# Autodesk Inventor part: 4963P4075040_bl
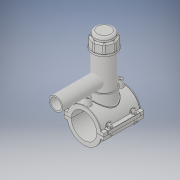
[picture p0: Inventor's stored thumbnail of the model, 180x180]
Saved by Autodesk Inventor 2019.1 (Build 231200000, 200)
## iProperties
Created: 2017-07
Part Number: 4963P4075040_bl
Material: Generic
Document SubType Name: Modeling
Designer: KIM
Density: 1 g/cm^3
Appearance: Default
Author: KIM
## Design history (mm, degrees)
derived "4963P4.ipt"
feature "Solid1::4963P4.ipt" dims "ScaleForDerivedMember" = 10
feature "Solid2::4963P4.ipt" dims "ScaleForDerivedMember" = 10
feature "Solid3::4963P4.ipt" dims "ScaleForDerivedMember" = 10
tag "TaggingFeature1"
body "Solid1"
body "Solid2"
body "Solid3"
other parameters: "d0" = 75 [user parameter], "d2" = 117 [user parameter], "d3" = 18.75 [user parameter], "d4" = 118 [user parameter], "d5" = 0 [user parameter], "d6" = 0.1 [user parameter], "d8" = 0 [user parameter], "d19" = 6 [user parameter], "d20" = 6 [user parameter], "d21" = 70.8 [user parameter], "d23" = 0 [user parameter], "d24" = 35.4 [user parameter], "d26" = 0 [user parameter], "d27" = 3 [user parameter], "d28" = 3 [user parameter], "d29" = 3 [user parameter], "d30" = 25 [user parameter], "d31" = 6 [user parameter], "d32" = 0 [user parameter], "d33" = 0 [user parameter], "d34" = 0.6 [user parameter], "d40" = 50.7 [user parameter], "d41" = 67.5 [user parameter], "d43" = 0 [user parameter], "d45" = 0 [user parameter], "d47" = 119.55 [user parameter], "d70" = 15 [user parameter], "d72" = 0 [user parameter], "d73" = 6 [user parameter], "d75" = 5 [user parameter], "d76" = 0 [user parameter], "d77" = 3.75 [user parameter], "d78" = 67.5 [user parameter], "d79" = 15 [user parameter], "d80" = 47.2 [user parameter], "d82" = 5 deg [user parameter], "d84" = 4 [user parameter], "d85" = 14 [user parameter], "d86" = 0 [user parameter], "d87" = 3 [user parameter], "d88" = 0 [user parameter], "d89" = 1 [user parameter], "d90" = 1 [user parameter], "d91" = 94.4 [user parameter], "d92" = 0 [user parameter], "d93" = 0.5 [user parameter], "d94" = 39.47368 [user parameter], "d96" = 99.45 [user parameter], "d97" = 2.36 [user parameter], "d98" = 0 [user parameter], "d102" = 0.75 [user parameter], "d120" = 140 deg [user parameter], "d121" = 24.228 [user parameter], "d122" = 20 deg [user parameter], "d123" = 195 [user parameter], "d124" = 58.5 [user parameter], "d126" = 0 [user parameter], "d143" = 77.25 [user parameter], "d145" = 17.30769 [user parameter], "d149" = 1.125 [user parameter], "d150" = 19.03846 [user parameter], "d153" = 118 [user parameter], "d154" = 0 [user parameter], "d156" = 48.75 [user parameter], "d157" = 160 deg [user parameter], "d159" = 4.5 [user parameter], "d161" = 1.125 [user parameter], "d162" = 70.8 [user parameter], "d163" = 0 [user parameter], "d164" = 37.5 [user parameter], "d167" = 7.5 [user parameter], "d168" = 47.56098 [user parameter], "d170" = 3.75 [user parameter], "d172" = 0 [user parameter], "d173" = 1 [user parameter], "d175" = 37.5 [user parameter], "d176" = 20 deg [user parameter], "d177" = 5.25 [user parameter], "d178" = 22.5 [user parameter], "d180" = 0 [user parameter], "d183" = 9 [user parameter], "d184" = 4.2 [user parameter], "d185" = 38.35 [user parameter], "d186" = 38.35 [user parameter], "d187" = 48.75 [user parameter], "d188" = 6.75 [user parameter], "d189" = 5.25 [user parameter], "d190" = 0 [user parameter], "d191" = 73.125 [user parameter], "d193" = 8 [user parameter], "d194" = 4.13 [user parameter], "d195" = 90 deg [user parameter], "d197" = 0 [user parameter], "d199" = 0 [user parameter], "d200" = 11.25 [user parameter], "d202" = 0 [user parameter], "d203" = 177 [user parameter], "d204" = 64.125 [user parameter], "d205" = 47.25 [user parameter], "d206" = 57.375 [user parameter], "d207" = 132.75 [user parameter], "d208" = 138.06 [user parameter], "d209" = 164.61 [user parameter], "d210" = 58.05 [user parameter], "d211" = 67.5 [user parameter], "d212" = 54 [user parameter], "d213" = 36 [user parameter], "d216" = 0 [user parameter], "d217" = 7.5 [user parameter], "d218" = 7.5 [user parameter], "d219" = 1.5 [user parameter], "d222" = 75 [user parameter], "d224" = 0 [user parameter], "d227" = 32 [user parameter], "d228" = 142 [user parameter], "d230" = 4.5 [user parameter], "d_" = 75 [user parameter], "B_" = 117 [user parameter], "L_" = 118 [user parameter], "d_t" = 6 [user parameter]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
